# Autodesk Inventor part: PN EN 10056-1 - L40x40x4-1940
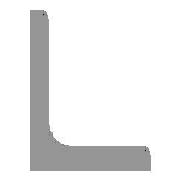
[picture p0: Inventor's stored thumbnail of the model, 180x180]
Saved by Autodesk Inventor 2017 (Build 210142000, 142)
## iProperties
IsCustomPart: 1
Created: 2020-07
Part Number: PN EN 10056-1 - L40x40x4-1940
Material: Stal, miękka
Description: Kątownik równoramienny
Document SubType Name: Modeling
Standard: PN
Designer: X
Standards Organization: PN
Language: pl-PL
Size Designation: L40x40x4
Categories: <MemberInstance><Categories><Category DisplayName="Kształtowniki konstrukcyjne" InternalName="089c4875-fa83-4c05-b084-43b9cc11f5ed" Mnemonic="GRDR"><CategoryPar
Stock Number: L40x40x4
Density: 7.85 g/cm^3
Appearance: Częściowo polerowana
Mass: 4688.44 g
Surface Area: 3010.24 cm^2
Volume: 597.254 cm^3
_CCFamilyMember: 70
_CCFamilyDisplayName: PN EN 10056-1 (Kątownik równoramienny) - Kątownik równoramienny
_FrameMemberDoc: Frame Member File
_Version: 15.0.0
_GetPNFromCC: 1
G_L: 1940,000 mm
G_W: 40,000 mm
G_H: 40,000 mm
Author: X
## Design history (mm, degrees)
node "Płaszczyzna początkowa"
node "Płaszczyzna końcowa"
sketch "Szkic2"
  geometry: L1 (-7.249, -1.249)-(-7.249, 25.751); L2 (-11.249, 28.751)-(-10.249, 28.751); L3 (-11.249, -11.249)-(-11.249, 28.751); L4 (-11.249, -11.249)-(28.751, -11.249); L5 (28.751, -10.249)-(28.751, -11.249); L6 (-1.249, -7.249)-(25.751, -7.249); L7 (0, 32.602)-(0, -17.123) reference; L8 (-17.123, 0)-(32.602, 0) reference; A1 r 6 centre (-1.249, -1.249) between (-7.249, -1.249) and (-1.249, -7.249); A2 r 3 centre (-10.249, 25.751) between (-7.249, 25.751) and (-10.249, 28.751); A3 r 3 centre (25.751, -10.249) between (28.751, -10.249) and (25.751, -7.249); 3 further points
  constraints: 12 end point, 6 point on circle, 6 point on line, 6 tangent, 3 centre point, 3 horizontal, 3 vertical, 1 equal radius
  dimensions: "d4" = 40 distance of L3.start L4.end (= b); "d6" = 40 distance of L3.start L2.start (= b); "d8" = 4 distance of point (28.751, -7.249) L4.end (= ParT); "d10" = 4 distance of L2.start point (-7.249, 28.751) (= ParT); "d17" = 6 radius of A1 (= R); "d18" = 3 radius of A2 (= R1); "d19" = 11.24871 distance between parallel lines of L8 L4 (= ex); "d20" = 11.24871 distance between parallel lines of L3 L7 (= d19)
extrude "Bryła" new body sketch "Szkic2" stored distance "d11" = 1940 (= G_L); taper "d12" = 0 deg
node "Driven Length"
  sketch "Sketch3"
    geometry: L1 (0, 0)-(10, 0) reference
    constraints: 2 end point, 1 horizontal
  workplane "Work Plane10"
  sketch "Sketch4"
    geometry: L1 (-2, 0)-(12, 0) reference; L2 (-2, 1940)-(12, 1940) reference
    dimensions: "d24" = 1940 distance between parallel lines of L1 L2 (derived)
body "Solid1"
other parameters: "b" = 40 [user parameter; used in 3 equation terms], "ParT" = 4 [user parameter; used in 3 equation terms], "R" = 6 [user parameter; used in 1 equation term], "R1" = 3 [user parameter; used in 1 equation term], "G_L" = 1940 (= d24) [user parameter; used in 1 equation term], "d7" = 4 (derived), "d9" = 4 (derived), "ex" = 11.24871 (computed from b, ParT) [user parameter; used in 1 equation term], "G_OFFSET_START" = 0 [user parameter; used in 1 equation term], "G_OFFSET_END" = 0 [user parameter; used in 1 equation term], "d21" = 0 (computed from G_OFFSET_START), "d23" = 90 deg
